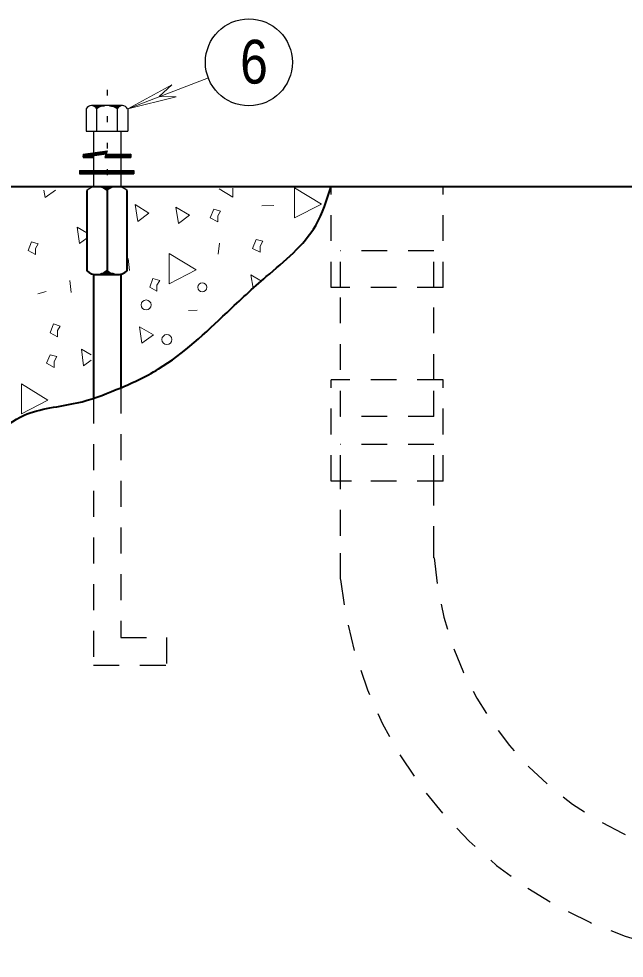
# Model space of a CAD drawing. Extents: x 312583 to 312854, y 144419 to 144597.
# Drawn here: x 312668.86 to 312679.38, y 144531.2 to 144547.51 of the extents above; entities that cross this region are included whole.
import ezdxf

# ---------------------------------------------------------------- set-up
doc = ezdxf.new("R2010")
doc.units = 0
doc.header["$LTSCALE"] = 0.3
doc.linetypes.add('DOTTED', pattern=[1.5, 0.3, -1.2])
doc.linetypes.add('SHORT_DASHED', pattern=[2.7, 1.5, -1.2])
doc.layers.add('1', color=7, linetype='Continuous', lineweight=25)
doc.layers.add('2', color=7, linetype='Continuous', lineweight=13)

msp = doc.modelspace()

# ---------------------------------------------------------------- linework, layer by layer
at = {"layer": '1', "linetype": 'DOTTED'}
msp.add_line((312670.3957, 144546.2789), (312670.3957, 144544.5999), dxfattribs=at)
at = {"layer": '1'}
for p, q in [((312670.0354, 144545.9493), (312670.0354, 144545.5583)), ((312670.1274, 144546.0106), (312670.6641, 144546.0106)), ((312670.2117, 144545.9493), (312670.2117, 144545.5583)), ((312670.5721, 144545.9493), (312670.5721, 144545.5583)), ((312670.7561, 144545.9493), (312670.7561, 144545.5583)), ((312670.0354, 144545.5583), (312670.7561, 144545.5583)), ((312670.1581, 144545.5583), (312670.1581, 144544.5999)), ((312670.6334, 144545.5583), (312670.6334, 144544.5999)), ((312669.9817, 144545.1596), (312669.9817, 144545.1059)), ((312670.3804, 144545.1596), (312670.8097, 144545.1596)), ((312670.8097, 144545.1596), (312670.8097, 144545.1059)), ((312670.3574, 144545.1059), (312670.8097, 144545.1059)), ((312669.9204, 144544.8759), (312670.8634, 144544.8759)), ((312669.9204, 144544.8759), (312669.9204, 144544.8223)), ((312669.9204, 144544.8683), (312670.8634, 144544.8683)), ((312669.9204, 144544.8529), (312670.8634, 144544.8529)), ((312669.9204, 144544.8376), (312670.8634, 144544.8376)), ((312669.9204, 144544.8223), (312670.8634, 144544.8223)), ((312670.8634, 144544.8759), (312670.8634, 144544.8223)), ((312670.1581, 144544.5999), (312670.6334, 144544.5999)), ((312670.2194, 144544.5999), (312670.5721, 144544.5999))]:
    msp.add_line(p, q, dxfattribs=at)
at = {"layer": '1', "lineweight": 40}
for p, q in [((312656.9791, 144544.5999), (312705.5321, 144544.5999)), ((312670.0431, 144544.5309), (312670.0431, 144543.1356)), ((312670.3957, 144544.5999), (312670.3957, 144543.0743)), ((312670.7407, 144544.5309), (312670.7407, 144543.1356)), ((312670.1581, 144543.0743), (312670.1581, 144540.9353)), ((312670.2194, 144543.0743), (312670.5721, 144543.0743)), ((312670.6334, 144543.0743), (312670.6334, 144541.1116))]:
    msp.add_line(p, q, dxfattribs=at)
at = {"layer": '1', "linetype": 'SHORT_DASHED'}
for p, q in [((312674.2904, 144542.8443), (312674.2904, 144544.5999)), ((312676.2377, 144542.8443), (312676.2377, 144544.5999)), ((312676.0767, 144543.4806), (312674.4514, 144543.4806)), ((312674.4514, 144542.8443), (312674.4514, 144543.4806)), ((312676.0767, 144542.8443), (312676.0767, 144543.4806)), ((312676.2377, 144542.8443), (312674.2904, 144542.8443)), ((312674.4514, 144540.6056), (312674.4514, 144542.8443)), ((312676.0767, 144541.2419), (312676.0767, 144542.8443)), ((312676.2377, 144541.2419), (312674.2904, 144541.2419)), ((312674.4514, 144540.6056), (312674.4514, 144541.2419)), ((312676.0767, 144540.6056), (312676.0767, 144541.2419)), ((312676.2377, 144539.4863), (312676.2377, 144541.2419)), ((312670.6334, 144541.1116), (312670.6334, 144536.7723)), ((312670.1581, 144540.9353), (312670.1581, 144536.2893)), ((312676.0767, 144540.6056), (312674.4514, 144540.6056)), ((312676.0767, 144540.1226), (312674.4514, 144540.1226)), ((312674.4514, 144539.4863), (312674.4514, 144540.1226)), ((312676.0767, 144539.4863), (312676.0767, 144540.1226)), ((312674.6431, 144539.4863), (312674.4207, 144539.4863)), ((312670.1581, 144536.2893), (312671.4307, 144536.2893))]:
    msp.add_line(p, q, dxfattribs=at)
at = {"layer": '1'}
for points in [[(312670.1504, 144546.0029), (312670.3497, 144546.0029), (312670.3114, 144545.9953), (312670.2884, 144545.9953), (312670.2577, 144545.9799), (312670.2194, 144545.9569), (312670.2041, 144545.9799), (312670.1887, 144545.9876), (312670.1581, 144546.0029), (312670.3344, 144546.0029), (312670.2807, 144545.9953), (312670.2424, 144545.9799), (312670.2194, 144545.9569), (312670.1887, 144545.9876), (312670.1657, 144546.0029), (312670.3114, 144546.0029), (312670.2577, 144545.9876), (312670.2194, 144545.9646), (312670.1811, 144545.9953), (312670.2961, 144546.0029), (312670.2194, 144545.9723), (312670.1887, 144545.9953), (312670.2807, 144545.9953), (312670.2117, 144545.9723), (312670.1964, 144545.9953), (312670.2654, 144545.9953), (312670.2194, 144545.9799), (312670.2041, 144545.9953), (312670.2501, 144545.9953), (312670.2194, 144545.9799), (312670.2117, 144545.9876), (312670.2347, 144545.9876), (312670.2194, 144545.9876)], [(312670.6411, 144546.0029), (312670.4417, 144546.0029), (312670.4724, 144545.9953), (312670.4954, 144545.9953), (312670.5337, 144545.9799), (312670.5721, 144545.9569), (312670.5874, 144545.9799), (312670.6027, 144545.9876), (312670.6334, 144546.0029), (312670.4571, 144546.0029), (312670.5031, 144545.9953), (312670.5414, 144545.9799), (312670.5721, 144545.9569), (312670.6027, 144545.9876), (312670.6181, 144546.0029), (312670.4801, 144546.0029), (312670.5261, 144545.9876), (312670.5721, 144545.9646), (312670.6104, 144545.9953), (312670.4954, 144546.0029), (312670.5721, 144545.9723), (312670.6027, 144545.9953), (312670.5031, 144545.9953), (312670.5721, 144545.9723), (312670.5951, 144545.9953), (312670.5184, 144545.9953), (312670.5721, 144545.9799), (312670.5874, 144545.9953), (312670.5414, 144545.9953), (312670.5721, 144545.9799), (312670.5797, 144545.9876), (312670.5567, 144545.9876), (312670.5721, 144545.9876)], [(312669.9817, 144545.1596), (312670.3957, 144545.2209), (312670.3574, 144545.1059)], [(312670.1581, 144545.1059), (312669.9817, 144545.1136), (312669.9894, 144545.1596), (312670.3804, 144545.2056), (312670.3727, 144545.1673), (312670.1504, 144545.1366), (312670.1504, 144545.1136), (312669.9894, 144545.1213), (312669.9894, 144545.1519), (312670.3727, 144545.1979), (312670.3651, 144545.1749), (312670.1427, 144545.1366), (312670.1427, 144545.1213), (312669.9971, 144545.1213), (312669.9971, 144545.1366), (312670.3574, 144545.1903), (312670.3574, 144545.1826), (312670.1427, 144545.1443), (312670.1351, 144545.1366), (312670.0891, 144545.1289), (312670.0047, 144545.1289), (312670.3497, 144545.1826), (312670.0584, 144545.1289)], [(312670.3804, 144545.1596), (312669.9817, 144545.1059), (312670.1581, 144545.1059)], [(312670.3727, 144545.1136), (312670.8021, 144545.1136), (312670.8021, 144545.1596), (312670.3804, 144545.1519), (312670.3727, 144545.1213), (312670.7944, 144545.1213), (312670.7944, 144545.1443), (312670.3881, 144545.1443), (312670.3804, 144545.1213), (312670.7867, 144545.1289), (312670.7791, 144545.1366), (312670.7791, 144545.1443), (312670.3881, 144545.1366), (312670.3881, 144545.1289), (312670.7791, 144545.1289)], [(312670.2654, 144544.5923), (312670.5261, 144544.5923), (312670.4954, 144544.5923), (312670.4647, 144544.5846), (312670.4417, 144544.5693), (312670.4187, 144544.5616), (312670.3957, 144544.5463), (312670.3957, 144544.5386), (312670.3497, 144544.5693), (312670.3037, 144544.5846), (312670.2807, 144544.5923), (312670.5031, 144544.5923), (312670.4877, 144544.5923), (312670.4647, 144544.5846), (312670.4417, 144544.5769), (312670.4111, 144544.5616), (312670.4034, 144544.5539), (312670.3957, 144544.5463), (312670.3497, 144544.5693), (312670.3037, 144544.5923), (312670.4724, 144544.5923), (312670.4341, 144544.5769), (312670.3957, 144544.5539), (312670.3191, 144544.5846), (312670.4571, 144544.5923), (312670.3957, 144544.5463), (312670.3344, 144544.5846), (312670.4417, 144544.5846), (312670.3957, 144544.5616), (312670.3574, 144544.5846), (312670.4264, 144544.5846), (312670.3957, 144544.5693), (312670.3574, 144544.5769), (312670.3804, 144544.5616), (312670.3881, 144544.5769), (312670.3881, 144544.5539), (312670.4111, 144544.5769), (312670.4187, 144544.5769), (312670.4264, 144544.5769)]]:
    msp.add_lwpolyline(points, dxfattribs=at)
at = {"layer": '1', "lineweight": 40}
msp.add_lwpolyline([(312670.2654, 144543.0743), (312670.5261, 144543.0743), (312670.4954, 144543.0819), (312670.4647, 144543.0896), (312670.4417, 144543.0973), (312670.4187, 144543.1126), (312670.3957, 144543.1279), (312670.3957, 144543.1279), (312670.3497, 144543.0973), (312670.3037, 144543.0819), (312670.2807, 144543.0743), (312670.5031, 144543.0743), (312670.4877, 144543.0743), (312670.4647, 144543.0819), (312670.4417, 144543.0896), (312670.4111, 144543.1049), (312670.4034, 144543.1126), (312670.3957, 144543.1279), (312670.3497, 144543.0973), (312670.3037, 144543.0743), (312670.4724, 144543.0743), (312670.4341, 144543.0896), (312670.3957, 144543.1126), (312670.3191, 144543.0819), (312670.4571, 144543.0819), (312670.3957, 144543.1203), (312670.3344, 144543.0819), (312670.4417, 144543.0819), (312670.3957, 144543.1049), (312670.3574, 144543.0896), (312670.4264, 144543.0896), (312670.3957, 144543.0973), (312670.3574, 144543.0896), (312670.3804, 144543.1049), (312670.3881, 144543.0896), (312670.3881, 144543.1126), (312670.4111, 144543.0973), (312670.4187, 144543.0896), (312670.4264, 144543.0896)], dxfattribs=at)
at = {"layer": '1', "linetype": 'SHORT_DASHED'}
for points in [[(312676.2377, 144539.4863), (312674.2904, 144539.4863), (312674.2904, 144541.2419)], [(312674.4514, 144537.7843), (312674.4514, 144538.5356), (312674.4514, 144539.4863)], [(312676.0767, 144538.1523), (312676.0767, 144538.2519), (312676.0767, 144539.4863)], [(312670.6334, 144536.7723), (312671.4307, 144536.7723), (312671.4307, 144536.2893)]]:
    msp.add_lwpolyline(points, dxfattribs=at)
at = {"layer": '1'}
for centre, radius, start, end in [((312670.1252, 144545.9078), 0.0993, 25.60064, 154.39936), ((312670.3938, 144545.6945), 0.3126, 55.04559, 124.95441), ((312670.6625, 144545.9078), 0.0993, 25.60064, 154.39936), ((312670.219, 144544.3253), 0.272, 50.00693, 129.99306), ((312670.5686, 144544.3253), 0.272, 50.00694, 129.99307)]:
    msp.add_arc(centre, radius, start, end, dxfattribs=at)
at = {"layer": '1', "lineweight": 40}
for centre, start, end in [((312670.219, 144543.3426), 230.00694, 309.99307), ((312670.5686, 144543.3426), 230.00693, 309.99306)]:
    msp.add_arc(centre, 0.272, start, end, dxfattribs=at)
at = {"layer": '1', "linetype": 'SHORT_DASHED'}
for centre, radius, start, end in [((312681.8142, 144538.5686), 5.75, 184.14986, 265.21724), ((312681.7871, 144538.5684), 7.3792, 186.13, 266.47596)]:
    msp.add_arc(centre, radius, start, end, dxfattribs=at)
at = {"layer": '1', "lineweight": 40}
msp.add_spline([(312661.7707, 144538.5816), (312662.8364, 144538.5586), (312663.4651, 144538.4359), (312664.1167, 144538.6123), (312664.8604, 144538.9113), (312665.6884, 144539.0569), (312666.0411, 144539.1489), (312666.4627, 144539.2639), (312666.9381, 144539.4709), (312667.3827, 144539.6549), (312668.4484, 144540.3066), (312668.9544, 144540.6286), (312669.8744, 144540.8433), (312670.5567, 144541.0733), (312671.2927, 144541.4336), (312672.4811, 144542.4149), (312673.1634, 144543.0359), (312674.0221, 144543.9253), (312674.2904, 144544.5999)], degree=3, dxfattribs=at)
at = {"layer": '2'}
for p, q in [((312672.1591, 144546.4859), (312670.7561, 144545.9493)), ((312670.7561, 144545.9493), (312671.5227, 144546.3633)), ((312671.5227, 144546.3633), (312671.3004, 144546.1639)), ((312670.7561, 144545.9493), (312671.5994, 144546.1563)), ((312671.5994, 144546.1563), (312671.3004, 144546.1639)), ((312669.2994, 144544.5386), (312669.3224, 144544.4083)), ((312669.3224, 144544.4083), (312669.4987, 144544.5386)), ((312672.3431, 144544.5616), (312672.5807, 144544.4159)), ((312672.5807, 144544.4159), (312672.5807, 144544.5693)), ((312673.0867, 144544.2626), (312673.2937, 144544.2703)), ((312669.9204, 144543.6109), (312670.0431, 144543.7029)), ((312672.3277, 144543.4269), (312672.3507, 144543.6186)), ((312670.7637, 144543.3503), (312670.7867, 144543.1433)), ((312669.7517, 144542.9669), (312669.7747, 144542.7599)), ((312669.1921, 144542.7369), (312669.3377, 144542.7753)), ((312671.8141, 144542.4456), (312671.9597, 144542.4533)), ((312669.9894, 144541.4873), (312670.1197, 144541.5869))]:
    msp.add_line(p, q, dxfattribs=at)
for points in [[(312673.6541, 144544.5769), (312673.6541, 144544.0556), (312674.1217, 144544.2933)], [(312670.9324, 144543.9943), (312671.1241, 144544.1399), (312670.8864, 144544.2856)], [(312671.6377, 144543.9559), (312671.8294, 144544.1016), (312671.5917, 144544.2396)], [(312672.3201, 144544.0939), (312672.3661, 144544.1706), (312672.2511, 144544.2089), (312672.1897, 144544.0556), (312672.3201, 144543.9866)], [(312669.1537, 144543.5266), (312669.1997, 144543.6033), (312669.0847, 144543.6416), (312669.0234, 144543.4883), (312669.1537, 144543.4193)], [(312673.0561, 144543.5649), (312673.1021, 144543.6493), (312672.9871, 144543.6799), (312672.9257, 144543.5266), (312673.0561, 144543.4576)], [(312671.4767, 144543.4346), (312671.4767, 144542.9133), (312671.9444, 144543.1509)], [(312671.2621, 144542.8903), (312671.3157, 144542.9669), (312671.1931, 144543.0053), (312671.1394, 144542.8519), (312671.2621, 144542.7829)], [(312669.5371, 144542.1006), (312669.5831, 144542.1773), (312669.4681, 144542.2156), (312669.4067, 144542.0623), (312669.5371, 144541.9933)], [(312671.0014, 144541.8783), (312671.2007, 144542.0239), (312670.9631, 144542.1619)], [(312669.4757, 144541.5639), (312669.5217, 144541.6483), (312669.4067, 144541.6789), (312669.3454, 144541.5333), (312669.4757, 144541.4566)], [(312668.9084, 144541.1729), (312668.9084, 144540.6516), (312669.3684, 144540.8893)]]:
    msp.add_lwpolyline(points, close=True, dxfattribs=at)
for points in [[(312670.0431, 144543.7949), (312669.8744, 144543.8946), (312669.9204, 144543.6109)], [(312673.0791, 144542.9593), (312672.8951, 144543.0666), (312672.9334, 144542.8366)], [(312670.1197, 144541.6789), (312669.9511, 144541.7786), (312669.9894, 144541.4873)]]:
    msp.add_lwpolyline(points, dxfattribs=at)
at = {"layer": '2', "lineweight": 25}
msp.add_circle((312672.8612, 144546.7562), 0.7557, dxfattribs=at)
at = {"layer": '2'}
for centre, radius in [((312672.0503, 144542.8508), 0.0784), ((312671.0747, 144542.5444), 0.0865), ((312671.4357, 144541.9432), 0.0865)]:
    msp.add_circle(centre, radius, dxfattribs=at)

# ---------------------------------------------------------------- texts
at = {"layer": '2', "width": 0.85}
msp.add_text('6', height=0.76, dxfattribs=at).set_placement((312672.7098, 144546.3869))

doc.saveas('drawing.dxf')
